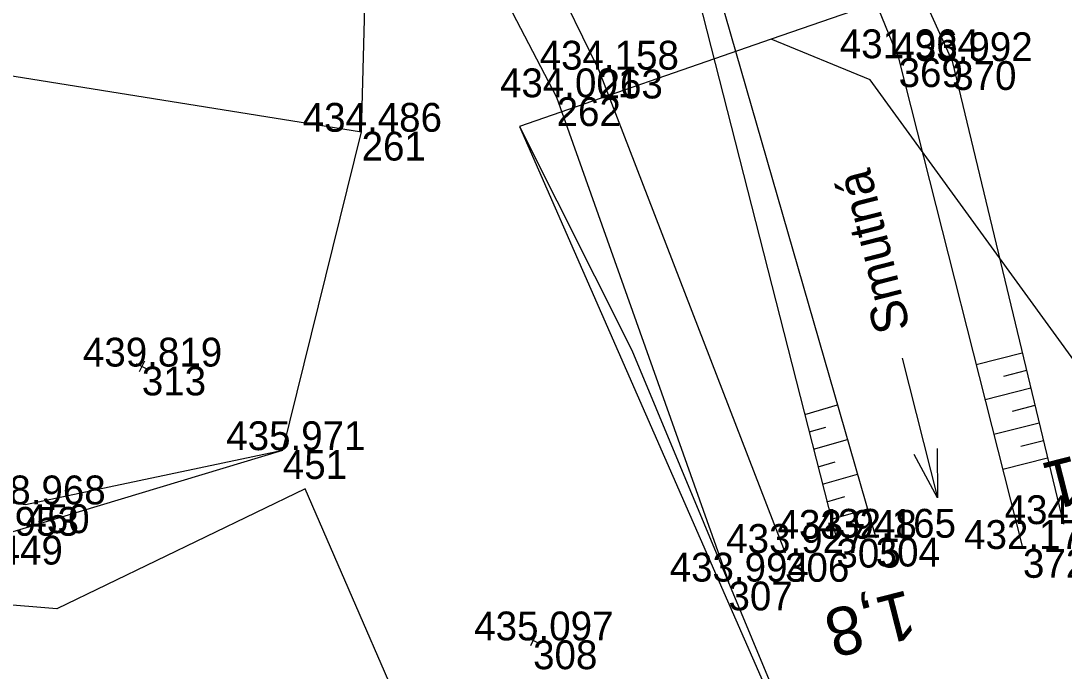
# Model space of a CAD drawing. Extents: x -776734 to -748832, y -1118122 to -976986.
# Drawn here: x -751174.08 to -751130.63, y -1114732.85 to -1114705.77 of the extents above; entities that cross this region are included whole.
import ezdxf

# ---------------------------------------------------------------- set-up
doc = ezdxf.new("R2010")
doc.units = 0
for name, color, linetype in [('KM_Hranice parcel', 7, 'Continuous'), ('SŽG Vrstva 48', 7, 'Continuous'), ('SŽG Vrstva 49', 7, 'Continuous'), ('SŽG Vrstva 50', 7, 'Continuous'), ('SŽG Vrstva 51', 7, 'Continuous'), ('SŽG Vrstva 53', 7, 'Continuous'), ('SŽG Vrstva 58', 7, 'Continuous'), ('SŽG Vrstva 60', 7, 'Continuous'), ('SŽG Vrstva 61', 7, 'Continuous')]:
    doc.layers.add(name, color=color, linetype=linetype)

msp = doc.modelspace()

# ---------------------------------------------------------------- linework, layer by layer
at = {"layer": 'KM_Hranice parcel'}
msp.add_line((-751134.08, -1114703.51), (-751142.83, -1114706.54), dxfattribs=at)
for points in [[(-751142.83, -1114706.54), (-751153.31, -1114710.17), (-751148.64, -1114719.49), (-751137.57, -1114746.06), (-751139.06, -1114746.27), (-751138.42, -1114748.17)], [(-751077.03, -1114776.29), (-751083.1, -1114764.47), (-751081.04, -1114740), (-751082.95, -1114737.73), (-751097.72, -1114741.14), (-751105.51, -1114739.93), (-751127.42, -1114723.76), (-751138.7, -1114708.23), (-751142.83, -1114706.54)], [(-751138.42, -1114748.17), (-751151.05, -1114751.02), (-751162.24, -1114725.26), (-751172.58, -1114730.25), (-751213.65, -1114726.85)]]:
    msp.add_lwpolyline(points, dxfattribs=at)
at = {"layer": 'SŽG Vrstva 48'}
for p, q in [((-751132.368, -1114719.605), (-751134.286, -1114720.091)), ((-751132.193, -1114720.334), (-751133.147, -1114720.576)), ((-751132.018, -1114721.064), (-751133.918, -1114721.545)), ((-751141.434, -1114722.157), (-751140.07, -1114721.764)), ((-751131.842, -1114721.793), (-751132.788, -1114722.033)), ((-751141.248, -1114722.884), (-751140.555, -1114722.684)), ((-751131.667, -1114722.522), (-751133.549, -1114722.999)), ((-751141.063, -1114723.611), (-751139.654, -1114723.205)), ((-751131.492, -1114723.252), (-751132.428, -1114723.489)), ((-751140.877, -1114724.338), (-751140.162, -1114724.132)), ((-751131.317, -1114723.981), (-751133.18, -1114724.453)), ((-751140.691, -1114725.065), (-751139.239, -1114724.647)), ((-751140.505, -1114725.792), (-751139.768, -1114725.58)), ((-751140.32, -1114726.519), (-751138.823, -1114726.088))]:
    msp.add_line(p, q, dxfattribs=at)
at = {"layer": 'SŽG Vrstva 49'}
for p, q in [((-751186.41, -1114706.153), (-751159.892, -1114710.39)), ((-751163.172, -1114723.646), (-751159.892, -1114710.39)), ((-751168.8213, -1114720.2756), (-751169.2707, -1114720.0564)), ((-751168.9364, -1114719.9413), (-751169.1556, -1114720.3907)), ((-751152.5223, -1114731.6766), (-751152.9717, -1114731.4574)), ((-751152.6374, -1114731.3423), (-751152.8566, -1114731.7917))]:
    msp.add_line(p, q, dxfattribs=at)
for points in [[(-751159.583, -1114669.179), (-751152.304, -1114674.09), (-751146.04, -1114682.559), (-751140.899, -1114695.046), (-751135.289, -1114707.45), (-751130.657, -1114726.726)], [(-751160.409, -1114669.901), (-751154.232, -1114677.23), (-751146.679, -1114684.603), (-751142.986, -1114693.954), (-751137.521, -1114707.329), (-751132.342, -1114727.761)], [(-751159.892, -1114710.39), (-751159.564, -1114697.887), (-751162.611, -1114687.691), (-751171.305, -1114676.437), (-751182.896, -1114671.724), (-751191.58, -1114672.907), (-751197.985, -1114678.047), (-751212.472, -1114698.152), (-751234.949, -1114713.279), (-751244.9, -1114718.575)], [(-751166.835, -1114672.143), (-751156.612, -1114681.118), (-751149.576, -1114689.282), (-751145.388, -1114703.319), (-751138.476, -1114727.292)], [(-751168.436, -1114673.733), (-751158.526, -1114682.859), (-751153.413, -1114687.89), (-751146.017, -1114704.22), (-751140.111, -1114727.336)], [(-751205.217, -1114723.182), (-751190.613, -1114723.681), (-751173.898, -1114725.903), (-751163.172, -1114723.646)], [(-751204.754, -1114724.609), (-751190.638, -1114725.023), (-751175.014, -1114727.21), (-751163.172, -1114723.646)]]:
    msp.add_lwpolyline(points, dxfattribs=at)
at = {"layer": 'SŽG Vrstva 50'}
for points in [[(-751160.409, -1114669.901), (-751154.232, -1114677.23), (-751146.679, -1114684.603), (-751142.986, -1114693.954), (-751137.521, -1114707.329), (-751132.342, -1114727.761)], [(-751166.835, -1114672.143), (-751156.612, -1114681.118), (-751149.576, -1114689.282), (-751145.388, -1114703.319), (-751138.476, -1114727.292)]]:
    msp.add_lwpolyline(points, dxfattribs=at)
at = {"layer": 'SŽG Vrstva 51'}
for points in [[(-751179.332, -1114665.61), (-751169.189, -1114674.547), (-751160.093, -1114686.607), (-751155.976, -1114695.63), (-751150.02, -1114707.804), (-751142.251, -1114727.926)], [(-751180.281, -1114667.838), (-751171.305, -1114676.437), (-751162.611, -1114687.691), (-751158.117, -1114696.777), (-751151.768, -1114708.954), (-751144.608, -1114729.118)]]:
    msp.add_lwpolyline(points, dxfattribs=at)
at = {"layer": 'SŽG Vrstva 53'}
msp.add_lwpolyline([(-751047.63, -1114693.52), (-751057.9, -1114691.02), (-751081.52, -1114685.27), (-751134.08, -1114703.51), (-751142.83, -1114706.54), (-751153.31, -1114710.17), (-751137.57, -1114746.06), (-751139.06, -1114746.27), (-751138.42, -1114748.17), (-751151.05, -1114751.02), (-751162.24, -1114725.26), (-751172.58, -1114730.25), (-751213.65, -1114726.85), (-751218.67, -1114726.44), (-751268.46, -1114745.82), (-751307.93, -1114762.77), (-751323.57, -1114769.49), (-751347.57, -1114777.14), (-751364.44, -1114782.53), (-751398.43, -1114791.82)], dxfattribs=at)
at = {"layer": 'SŽG Vrstva 58'}
msp.add_line((-751137.3771, -1114719.821), (-751135.9029, -1114725.637), dxfattribs=at)
msp.add_lwpolyline([(-751135.9096, -1114723.5755), (-751135.9029, -1114725.637), (-751136.879, -1114723.8212)], dxfattribs=at)
at = {"layer": 'SŽG Vrstva 60'}
for p, q in [((-751137.521, -1114707.329), (-751137.521, -1114707.329)), ((-751135.289, -1114707.45), (-751135.289, -1114707.45)), ((-751150.02, -1114707.804), (-751150.02, -1114707.804)), ((-751151.768, -1114708.954), (-751151.768, -1114708.954)), ((-751159.892, -1114710.39), (-751159.892, -1114710.39)), ((-751169.046, -1114720.166), (-751169.046, -1114720.166)), ((-751163.172, -1114723.646), (-751163.172, -1114723.646)), ((-751173.898, -1114725.903), (-751173.898, -1114725.903)), ((-751130.657, -1114726.726), (-751130.657, -1114726.726)), ((-751140.111, -1114727.336), (-751140.111, -1114727.336)), ((-751138.476, -1114727.292), (-751138.476, -1114727.292)), ((-751142.251, -1114727.926), (-751142.251, -1114727.926)), ((-751132.342, -1114727.761), (-751132.342, -1114727.761)), ((-751144.608, -1114729.118), (-751144.608, -1114729.118)), ((-751152.747, -1114731.567), (-751152.747, -1114731.567))]:
    msp.add_line(p, q, dxfattribs=at)

# ---------------------------------------------------------------- texts
at = {"layer": 'SŽG Vrstva 48'}
for s, rotation, p in [('2,1', 194.22348, (-751128.029, -1114723.307)), ('1,8', 194.33213, (-751137.132, -1114729.457))]:
    msp.add_text(s, height=2, rotation=rotation, dxfattribs=at).set_placement(p)
at = {"layer": 'SŽG Vrstva 58'}
msp.add_text('Smutná', height=1.5, rotation=104.22348, dxfattribs=at).set_placement((-751137.027, -1114718.559))
at = {"layer": 'SŽG Vrstva 60'}
for s, p in [('369', (-751137.521, -1114708.529)), ('370', (-751135.289, -1114708.65)), ('263', (-751150.02, -1114709.004)), ('262', (-751151.768, -1114710.154)), ('261', (-751159.892, -1114711.59)), ('313', (-751169.046, -1114721.366)), ('451', (-751163.172, -1114724.846)), ('450', (-751173.898, -1114727.103)), ('449', (-751175.014, -1114728.41)), ('305', (-751140.111, -1114728.536)), ('304', (-751138.476, -1114728.492)), ('306', (-751142.251, -1114729.126)), ('372', (-751132.342, -1114728.961)), ('307', (-751144.608, -1114730.318)), ('308', (-751152.747, -1114732.767))]:
    msp.add_text(s, height=1.2, dxfattribs=at).set_placement(p)
at = {"layer": 'SŽG Vrstva 61'}
for s, p in [('431.964', (-751139.972, -1114707.329)), ('433.992', (-751137.7372, -1114707.45)), ('434.158', (-751152.4737, -1114707.804)), ('434.001', (-751154.1254, -1114708.954)), ('434.486', (-751162.3439, -1114710.39)), ('439.819', (-751171.4997, -1114720.166)), ('435.971', (-751165.5294, -1114723.646)), ('438.968', (-751176.3517, -1114725.903)), ('434.292', (-751133.1052, -1114726.726)), ('439.953', (-751177.4659, -1114727.21)), ('433.948', (-751142.5647, -1114727.336)), ('432.165', (-751140.9321, -1114727.292)), ('433.927', (-751144.7029, -1114727.926)), ('432.174', (-751134.793, -1114727.761)), ('433.994', (-751147.059, -1114729.118)), ('435.097', (-751155.1989, -1114731.567))]:
    msp.add_text(s, height=1.2, dxfattribs=at).set_placement(p)

doc.saveas('drawing.dxf')
